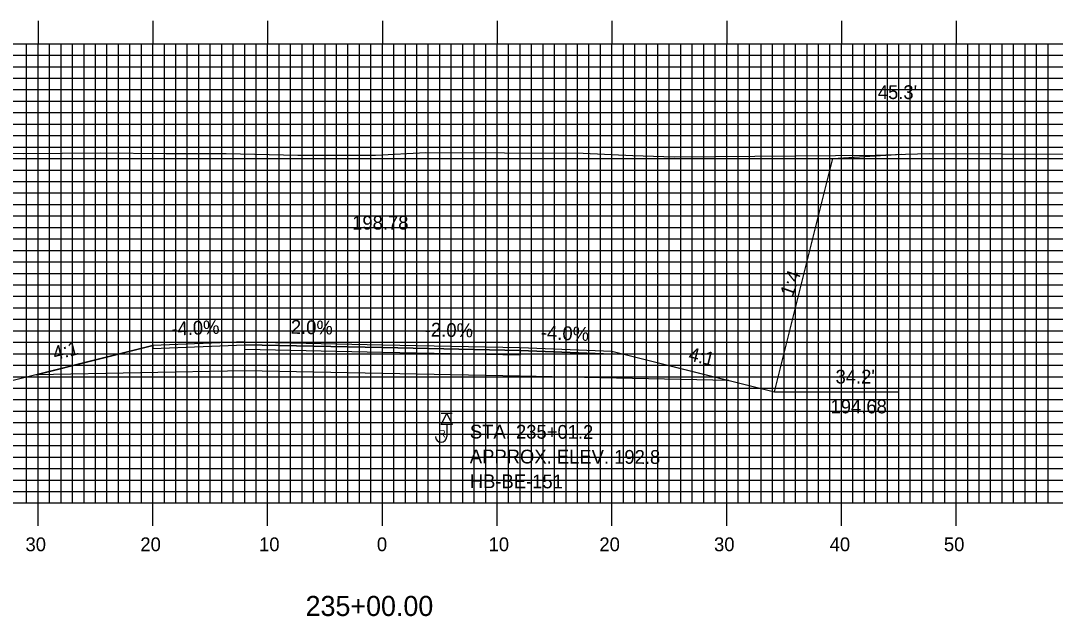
# Model space of a CAD drawing. Extents: x 1800355 to 1800699, y 442591 to 442811.
# Drawn here: x 1800489.5 to 1800579.7, y 442653.8 to 442705.7 of the extents above; entities that cross this region are included whole.
import ezdxf

# ---------------------------------------------------------------- set-up
doc = ezdxf.new("R2010")
doc.units = 0
for name, color, linetype in [('ANNOTATION', 7, 'Continuous'), ('BORING - REFUSAL', 7, 'Continuous'), ('D_Roadway_Centerline', 7, 'Continuous'), ('D_Roadway_Centerline_Text', 7, 'Continuous'), ('D_Roadway_Edge_Shoulder', 7, 'Continuous'), ('D_Roadway_Edge_TW', 7, 'Continuous'), ('D_Roadway_Pavement', 7, 'Continuous'), ('D_Roadway_SlopeLines', 7, 'Continuous'), ('D_Roadway_SubGrade', 7, 'Continuous'), ('D_Text_Standard', 7, 'Continuous'), ('H_V ANNOTATION', 7, 'Continuous'), ('MAJOR', 7, 'Continuous'), ('MINOR', 7, 'Continuous'), ('PDRAIN', 7, 'Continuous'), ('S_Roadway_Centerline', 7, 'Continuous')]:
    doc.layers.add(name, color=color, linetype=linetype)

msp = doc.modelspace()

# ---------------------------------------------------------------- linework, layer by layer
at = {"layer": 'BORING - REFUSAL'}
for p, q in [((1800527.116, 442671.465), (1800526.156, 442671.465)), ((1800526.636, 442670.506), (1800526.636, 442669.447))]:
    msp.add_line(p, q, dxfattribs=at)
msp.add_lwpolyline([(1800526.636, 442671.465), (1800527.116, 442670.506), (1800526.156, 442670.506)], close=True, dxfattribs=at)
msp.add_arc((1800526.151, 442669.447), 0.485, 180, 0, dxfattribs=at)
at = {"layer": 'D_Roadway_Edge_Shoulder'}
for points in [[(1800509.036, 442677.689), (1800501.036, 442677.369), (1800501.036, 442677.119), (1800509.036, 442677.439)], [(1800533.036, 442677.209), (1800541.036, 442676.889), (1800541.036, 442676.639), (1800533.036, 442676.959)]]:
    msp.add_lwpolyline(points, close=True, dxfattribs=at)
at = {"layer": 'D_Roadway_Edge_TW'}
msp.add_lwpolyline([(1800509.036, 442677.439), (1800509.036, 442677.689), (1800521.036, 442677.449), (1800533.036, 442677.209), (1800533.036, 442676.959), (1800521.036, 442677.199)], close=True, dxfattribs=at)
at = {"layer": 'D_Roadway_Pavement'}
msp.add_lwpolyline([(1800509.036, 442677.022), (1800509.036, 442677.439), (1800521.036, 442677.199), (1800533.036, 442676.959), (1800533.036, 442676.542), (1800521.036, 442676.782)], close=True, dxfattribs=at)
at = {"layer": 'D_Roadway_SlopeLines'}
msp.add_line((1800560.29, 442693.665), (1800566.29, 442694.042), dxfattribs=at)
for points in [[(1800555.21, 442673.345), (1800560.29, 442693.665)], [(1800501.036, 442677.369), (1800486.862, 442673.825)], [(1800541.036, 442676.889), (1800555.21, 442673.345)]]:
    msp.add_lwpolyline(points, dxfattribs=at)
at = {"layer": 'D_Roadway_SubGrade'}
msp.add_lwpolyline([(1800509.036, 442675.189), (1800490.862, 442674.825), (1800501.036, 442677.369), (1800501.036, 442677.119), (1800509.036, 442677.439), (1800521.036, 442677.199), (1800533.036, 442676.959), (1800541.036, 442676.639), (1800541.036, 442676.889), (1800551.21, 442674.345), (1800533.036, 442674.709), (1800521.036, 442674.949)], close=True, dxfattribs=at)
at = {"layer": 'MAJOR'}
for p, q in [((1800491.036, 442705.669), (1800491.036, 442703.665)), ((1800501.036, 442705.669), (1800501.036, 442703.665)), ((1800511.036, 442705.669), (1800511.036, 442703.665)), ((1800521.036, 442705.669), (1800521.036, 442703.665)), ((1800531.036, 442705.669), (1800531.036, 442703.665)), ((1800541.036, 442705.669), (1800541.036, 442703.665)), ((1800551.036, 442705.669), (1800551.036, 442703.665)), ((1800561.036, 442705.669), (1800561.036, 442703.665)), ((1800571.036, 442705.669), (1800571.036, 442703.665)), ((1800381.036, 442703.665), (1800661.036, 442703.665)), ((1800381.036, 442703.665), (1800661.036, 442703.665)), ((1800491.036, 442663.665), (1800491.036, 442703.665)), ((1800501.036, 442663.665), (1800501.036, 442703.665)), ((1800511.036, 442663.665), (1800511.036, 442703.665)), ((1800521.036, 442663.665), (1800521.036, 442703.665)), ((1800531.036, 442663.665), (1800531.036, 442703.665)), ((1800541.036, 442663.665), (1800541.036, 442703.665)), ((1800551.036, 442663.665), (1800551.036, 442703.665)), ((1800561.036, 442663.665), (1800561.036, 442703.665)), ((1800571.036, 442663.665), (1800571.036, 442703.665)), ((1800381.036, 442698.665), (1800661.036, 442698.665)), ((1800381.036, 442693.665), (1800661.036, 442693.665)), ((1800381.036, 442688.665), (1800661.036, 442688.665)), ((1800381.036, 442683.665), (1800661.036, 442683.665)), ((1800381.036, 442678.665), (1800661.036, 442678.665)), ((1800381.036, 442673.665), (1800661.036, 442673.665)), ((1800381.036, 442668.665), (1800661.036, 442668.665)), ((1800381.036, 442663.665), (1800661.036, 442663.665)), ((1800381.036, 442663.665), (1800661.036, 442663.665)), ((1800491.036, 442661.661), (1800491.036, 442663.665)), ((1800501.036, 442661.661), (1800501.036, 442663.665)), ((1800511.036, 442661.661), (1800511.036, 442663.665)), ((1800521.036, 442661.661), (1800521.036, 442663.665)), ((1800531.036, 442661.661), (1800531.036, 442663.665)), ((1800541.036, 442661.661), (1800541.036, 442663.665)), ((1800551.036, 442661.661), (1800551.036, 442663.665)), ((1800561.036, 442661.661), (1800561.036, 442663.665)), ((1800571.036, 442661.661), (1800571.036, 442663.665))]:
    msp.add_line(p, q, dxfattribs=at)
at = {"layer": 'MINOR'}
for p, q in [((1800490.036, 442663.665), (1800490.036, 442703.665)), ((1800492.036, 442663.665), (1800492.036, 442703.665)), ((1800493.036, 442663.665), (1800493.036, 442703.665)), ((1800494.036, 442663.665), (1800494.036, 442703.665)), ((1800495.036, 442663.665), (1800495.036, 442703.665)), ((1800496.036, 442663.665), (1800496.036, 442703.665)), ((1800497.036, 442663.665), (1800497.036, 442703.665)), ((1800498.036, 442663.665), (1800498.036, 442703.665)), ((1800499.036, 442663.665), (1800499.036, 442703.665)), ((1800500.036, 442663.665), (1800500.036, 442703.665)), ((1800502.036, 442663.665), (1800502.036, 442703.665)), ((1800503.036, 442663.665), (1800503.036, 442703.665)), ((1800504.036, 442663.665), (1800504.036, 442703.665)), ((1800505.036, 442663.665), (1800505.036, 442703.665)), ((1800506.036, 442663.665), (1800506.036, 442703.665)), ((1800507.036, 442663.665), (1800507.036, 442703.665)), ((1800508.036, 442663.665), (1800508.036, 442703.665)), ((1800509.036, 442663.665), (1800509.036, 442703.665)), ((1800510.036, 442663.665), (1800510.036, 442703.665)), ((1800512.036, 442663.665), (1800512.036, 442703.665)), ((1800513.036, 442663.665), (1800513.036, 442703.665)), ((1800514.036, 442663.665), (1800514.036, 442703.665)), ((1800515.036, 442663.665), (1800515.036, 442703.665)), ((1800516.036, 442663.665), (1800516.036, 442703.665)), ((1800517.036, 442663.665), (1800517.036, 442703.665)), ((1800518.036, 442663.665), (1800518.036, 442703.665)), ((1800519.036, 442663.665), (1800519.036, 442703.665)), ((1800520.036, 442663.665), (1800520.036, 442703.665)), ((1800522.036, 442663.665), (1800522.036, 442703.665)), ((1800523.036, 442663.665), (1800523.036, 442703.665)), ((1800524.036, 442663.665), (1800524.036, 442703.665)), ((1800525.036, 442663.665), (1800525.036, 442703.665)), ((1800526.036, 442663.665), (1800526.036, 442703.665)), ((1800527.036, 442663.665), (1800527.036, 442703.665)), ((1800528.036, 442663.665), (1800528.036, 442703.665)), ((1800529.036, 442663.665), (1800529.036, 442703.665)), ((1800530.036, 442663.665), (1800530.036, 442703.665)), ((1800532.036, 442663.665), (1800532.036, 442703.665)), ((1800533.036, 442663.665), (1800533.036, 442703.665)), ((1800534.036, 442663.665), (1800534.036, 442703.665)), ((1800535.036, 442663.665), (1800535.036, 442703.665)), ((1800536.036, 442663.665), (1800536.036, 442703.665)), ((1800537.036, 442663.665), (1800537.036, 442703.665)), ((1800538.036, 442663.665), (1800538.036, 442703.665)), ((1800539.036, 442663.665), (1800539.036, 442703.665)), ((1800540.036, 442663.665), (1800540.036, 442703.665)), ((1800542.036, 442663.665), (1800542.036, 442703.665)), ((1800543.036, 442663.665), (1800543.036, 442703.665)), ((1800544.036, 442663.665), (1800544.036, 442703.665)), ((1800545.036, 442663.665), (1800545.036, 442703.665)), ((1800546.036, 442663.665), (1800546.036, 442703.665)), ((1800547.036, 442663.665), (1800547.036, 442703.665)), ((1800548.036, 442663.665), (1800548.036, 442703.665)), ((1800549.036, 442663.665), (1800549.036, 442703.665)), ((1800550.036, 442663.665), (1800550.036, 442703.665)), ((1800552.036, 442663.665), (1800552.036, 442703.665)), ((1800553.036, 442663.665), (1800553.036, 442703.665)), ((1800554.036, 442663.665), (1800554.036, 442703.665)), ((1800555.036, 442663.665), (1800555.036, 442703.665)), ((1800556.036, 442663.665), (1800556.036, 442703.665)), ((1800557.036, 442663.665), (1800557.036, 442703.665)), ((1800558.036, 442663.665), (1800558.036, 442703.665)), ((1800559.036, 442663.665), (1800559.036, 442703.665)), ((1800560.036, 442663.665), (1800560.036, 442703.665)), ((1800562.036, 442663.665), (1800562.036, 442703.665)), ((1800563.036, 442663.665), (1800563.036, 442703.665)), ((1800564.036, 442663.665), (1800564.036, 442703.665)), ((1800565.036, 442663.665), (1800565.036, 442703.665)), ((1800566.036, 442663.665), (1800566.036, 442703.665)), ((1800567.036, 442663.665), (1800567.036, 442703.665)), ((1800568.036, 442663.665), (1800568.036, 442703.665)), ((1800569.036, 442663.665), (1800569.036, 442703.665)), ((1800570.036, 442663.665), (1800570.036, 442703.665)), ((1800572.036, 442663.665), (1800572.036, 442703.665)), ((1800573.036, 442663.665), (1800573.036, 442703.665)), ((1800574.036, 442663.665), (1800574.036, 442703.665)), ((1800575.036, 442663.665), (1800575.036, 442703.665)), ((1800576.036, 442663.665), (1800576.036, 442703.665)), ((1800577.036, 442663.665), (1800577.036, 442703.665)), ((1800578.036, 442663.665), (1800578.036, 442703.665)), ((1800579.036, 442663.665), (1800579.036, 442703.665)), ((1800381.036, 442702.665), (1800661.036, 442702.665)), ((1800381.036, 442701.665), (1800661.036, 442701.665)), ((1800381.036, 442700.665), (1800661.036, 442700.665)), ((1800381.036, 442699.665), (1800661.036, 442699.665)), ((1800381.036, 442697.665), (1800661.036, 442697.665)), ((1800381.036, 442696.665), (1800661.036, 442696.665)), ((1800381.036, 442695.665), (1800661.036, 442695.665)), ((1800381.036, 442694.665), (1800661.036, 442694.665)), ((1800381.036, 442692.665), (1800661.036, 442692.665)), ((1800381.036, 442691.665), (1800661.036, 442691.665)), ((1800381.036, 442690.665), (1800661.036, 442690.665)), ((1800381.036, 442689.665), (1800661.036, 442689.665)), ((1800381.036, 442687.665), (1800661.036, 442687.665)), ((1800381.036, 442686.665), (1800661.036, 442686.665)), ((1800381.036, 442685.665), (1800661.036, 442685.665)), ((1800381.036, 442684.665), (1800661.036, 442684.665)), ((1800381.036, 442682.665), (1800661.036, 442682.665)), ((1800381.036, 442681.665), (1800661.036, 442681.665)), ((1800381.036, 442680.665), (1800661.036, 442680.665)), ((1800381.036, 442679.665), (1800661.036, 442679.665)), ((1800381.036, 442677.665), (1800661.036, 442677.665)), ((1800381.036, 442676.665), (1800661.036, 442676.665)), ((1800381.036, 442675.665), (1800661.036, 442675.665)), ((1800381.036, 442674.665), (1800661.036, 442674.665)), ((1800381.036, 442672.665), (1800661.036, 442672.665)), ((1800381.036, 442671.665), (1800661.036, 442671.665)), ((1800381.036, 442670.665), (1800661.036, 442670.665)), ((1800381.036, 442669.665), (1800661.036, 442669.665)), ((1800381.036, 442667.665), (1800661.036, 442667.665)), ((1800381.036, 442666.665), (1800661.036, 442666.665)), ((1800381.036, 442665.665), (1800661.036, 442665.665)), ((1800381.036, 442664.665), (1800661.036, 442664.665))]:
    msp.add_line(p, q, dxfattribs=at)
at = {"layer": 'PDRAIN'}
msp.add_line((1800555.21, 442673.345), (1800565.981, 442673.345), dxfattribs=at)
at = {"layer": 'S_Roadway_Centerline'}
msp.add_lwpolyline([(1800436.574, 442693.94), (1800454.393, 442693.866), (1800461.415, 442693.85), (1800463.872, 442693.891), (1800472.397, 442694.01), (1800480.936, 442694.09), (1800485.149, 442694.12), (1800489.756, 442694.101), (1800496.494, 442694.173), (1800502.168, 442694.089), (1800507.432, 442694.113), (1800513.661, 442693.957), (1800520.432, 442693.96), (1800524.831, 442694.177), (1800538.537, 442694.137), (1800542.855, 442693.922), (1800546.465, 442693.823), (1800564.019, 442693.971), (1800566.604, 442694.051), (1800568.72, 442694.117), (1800587.563, 442694.007)], dxfattribs=at)

# ---------------------------------------------------------------- texts
at = {"layer": 'ANNOTATION'}
for s, rotation, p in [('1:4', 70.51601, (1800556.784, 442681.552)), ('1:4', 70.51601, (1800556.784, 442681.552)), ('-4.0%', 2.29061, (1800502.668, 442678.236)), ('2.0%', 358.85424, (1800513.043, 442678.409)), ('-2.0%', 358.85424, (1800524.722, 442678.175)), ('-4.0%', 357.70939, (1800534.828, 442677.939)), ('4:1', 14.03624, (1800492.485, 442676.093)), ('4:1', 345.96376, (1800547.629, 442676.102))]:
    msp.add_text(s, height=1.2, rotation=rotation, dxfattribs=at).set_placement(p)
for s, p in [("34.2'", (1800560.52, 442674.071)), ('194.68', (1800560.082, 442671.471))]:
    msp.add_text(s, height=1.2, dxfattribs=at).set_placement(p)
at = {"layer": 'BORING - REFUSAL'}
msp.add_text('R', height=0.64, dxfattribs=at).set_placement((1800525.927, 442669.391))
for s, p in [('STA. 235+01.2', (1800528.659, 442669.284)), ('APPROX. ELEV. 192.8', (1800528.652, 442667.124)), ('HB-BE-151', (1800528.645, 442664.964))]:
    msp.add_text(s, height=1.2, rotation=359.81416, dxfattribs=at).set_placement(p)
at = {"layer": 'D_Roadway_Centerline'}
for s, p in [('C', (1800521.031, 442677.449)), ('L', (1800521.036, 442677.441))]:
    msp.add_text(s, height=0.0146, dxfattribs=at).set_placement(p)
at = {"layer": 'D_Roadway_Centerline_Text'}
msp.add_text('198.78', height=1.2, dxfattribs=at).set_placement((1800518.398, 442687.479))
at = {"layer": 'D_Text_Standard'}
msp.add_text("45.3'", height=1.2, dxfattribs=at).set_placement((1800564.203, 442698.844))
at = {"layer": 'H_V ANNOTATION'}
for s, height, p in [('30', 1.2, (1800489.934, 442659.465)), ('20', 1.2, (1800499.944, 442659.465)), ('10', 1.2, (1800510.287, 442659.465)), ('0', 1.2, (1800520.554, 442659.465)), ('10', 1.2, (1800530.287, 442659.465)), ('20', 1.2, (1800539.944, 442659.465)), ('30', 1.2, (1800549.934, 442659.465)), ('40', 1.2, (1800560.008, 442659.465)), ('50', 1.2, (1800569.965, 442659.465)), ('235+00.00', 1.75, (1800514.341, 442653.821))]:
    msp.add_text(s, height=height, dxfattribs=at).set_placement(p)

doc.saveas('drawing.dxf')
